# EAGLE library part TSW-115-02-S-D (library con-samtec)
THROUGH-HOLE .025" SQ POST HEADER Source: Samtec TSW.pdf
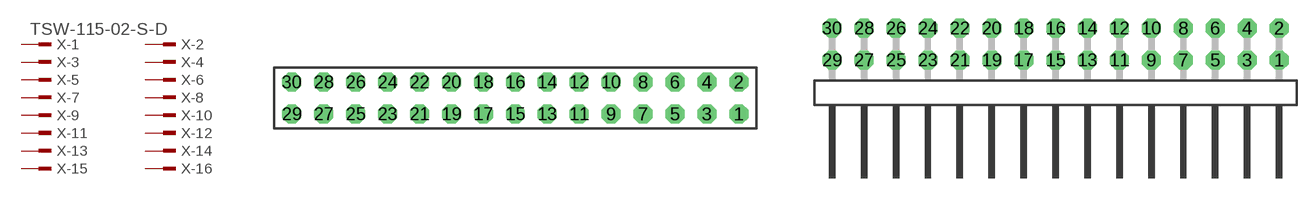
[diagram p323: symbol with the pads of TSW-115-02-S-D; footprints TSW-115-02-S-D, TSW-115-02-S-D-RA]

Designator prefix X; gates -1=MPINV -2=MPIN -3=MPIN -4=MPIN -5=MPIN -6=MPIN -7=MPIN -8=MPIN -9=MPIN -10=MPIN -11=MPIN -12=MPIN -13=MPIN -14=MPIN -15=MPIN -16=MPIN -17=MPIN -18=MPIN -19=MPIN -20=MPIN -21=MPIN -22=MPIN -23=MPIN -24=MPIN -25=MPIN -26=MPIN -27=MPIN -28=MPIN -29=MPIN -30=MPIN

## TSW-115-02-S-D (OC_FARNELL: unknown; OC_NEWARK: unknown)  [TSW-115-02-S-D]
1  -1:1  pas
2  -2:1  pas
3  -3:1  pas
4  -4:1  pas
5  -5:1  pas
6  -6:1  pas
7  -7:1  pas
8  -8:1  pas
9  -9:1  pas
10  -10:1  pas
11  -11:1  pas
12  -12:1  pas
13  -13:1  pas
14  -14:1  pas
15  -15:1  pas
16  -16:1  pas
17  -17:1  pas
18  -18:1  pas
19  -19:1  pas
20  -20:1  pas
21  -21:1  pas
22  -22:1  pas
23  -23:1  pas
24  -24:1  pas
25  -25:1  pas
26  -26:1  pas
27  -27:1  pas
28  -28:1  pas
29  -29:1  pas
30  -30:1  pas

## TSW-115-02-S-D-RA (OC_FARNELL: unknown; OC_NEWARK: unknown)  [TSW-115-02-S-D-RA]
Pads as for TSW-115-02-S-D

## Footprint TSW-115-02-S-D (pad centres in mm)
THROUGH-HOLE .025" SQ POST HEADER Source: Samtec TSW.pdf
drill 1 pad 1.5 octagon: 1 17.78,-1.27; 2 17.78,1.27; 3 15.24,-1.27; 4 15.24,1.27; 5 12.7,-1.27; 6 12.7,1.27; 7 10.16,-1.27; 8 10.16,1.27; 9 7.62,-1.27; 10 7.62,1.27; 11 5.08,-1.27; 12 5.08,1.27; 13 2.54,-1.27; 14 2.54,1.27; 15 0,-1.27; 16 0,1.27; 17 -2.54,-1.27; 18 -2.54,1.27; 19 -5.08,-1.27; 20 -5.08,1.27; 21 -7.62,-1.27; 22 -7.62,1.27; 23 -10.16,-1.27; 24 -10.16,1.27; 25 -12.7,-1.27; 26 -12.7,1.27; 27 -15.24,-1.27; 28 -15.24,1.27; 29 -17.78,-1.27; 30 -17.78,1.27

## Footprint TSW-115-02-S-D-RA (pad centres in mm)
THROUGH-HOLE .025" SQ POST HEADER Source: Samtec TSW.pdf
drill 1 pad 1.5 octagon: 1 17.78,1.524; 2 17.78,4.064; 3 15.24,1.524; 4 15.24,4.064; 5 12.7,1.524; 6 12.7,4.064; 7 10.16,1.524; 8 10.16,4.064; 9 7.62,1.524; 10 7.62,4.064; 11 5.08,1.524; 12 5.08,4.064; 13 2.54,1.524; 14 2.54,4.064; 15 0,1.524; 16 0,4.064; 17 -2.54,1.524; 18 -2.54,4.064; 19 -5.08,1.524; 20 -5.08,4.064; 21 -7.62,1.524; 22 -7.62,4.064; 23 -10.16,1.524; 24 -10.16,4.064; 25 -12.7,1.524; 26 -12.7,4.064; 27 -15.24,1.524; 28 -15.24,4.064; 29 -17.78,1.524; 30 -17.78,4.064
